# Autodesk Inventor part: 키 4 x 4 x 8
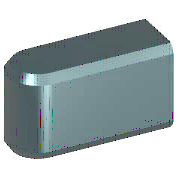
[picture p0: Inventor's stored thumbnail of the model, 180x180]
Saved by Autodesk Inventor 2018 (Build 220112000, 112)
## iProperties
Created: 2012-02
Part Number: 키 4 x 4 x 8
Material: 강철, 연강
Description: 키 및 해당 키홈
Document SubType Name: Modeling
Standard: KS B 1311
Designer: mduedu
Standards Organization: KS
Language: ko-KR
Size Designation: 4 x 4 x 8
Categories: <MemberInstance><Categories><Category DisplayName="샤프트 부품" InternalName="7f7aeb1f-a693-4053-b835-cee3144e0d98" Mnemonic="SHFT"><Category DisplayName="키" Interna
Density: 7.85 g/cm^3
Appearance: 노란색
Mass: 0.94205 g
Surface Area: 1.44138 cm^2
Volume: 0.120006 cm^3
IsCustomPart: 1
Author: mduedu
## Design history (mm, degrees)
sketch "스케치1"
  geometry: L1 (2, 2)-(8, 2); L2 (8, 2)-(8, -2); L3 (8, -2)-(2, -2); L4 (0, 7)-(0, -7) reference; L5 (-5, 0)-(30, 0) reference; A1 r 2 centre (2, 0) between (2, 2) and (2, -2)
  constraints: 6 end point, 3 tangent, 2 point on circle, 1 centre point, 1 horizontal, 1 parallel, 1 perpendicular, 1 point on line
  dimensions: "d0" = 2 radius of A1 (= 0.5 x PB); "d7" = 8 distance between parallel lines of L2 L4 (= NLG)
workplane "Work Plane1"
workplane "Work Plane2"
extrude "본체1" new body sketch "스케치1" taper "d3" = 0 deg; stored distance "d4" = 10
workaxis "Work Axis1"
workplane "Work Plane4"
body "Solid1"
chamfer "모따기1" distance "d8" = 0.25 (= PHH); stored, may be unused: second distance "d9" = 0.25 (= PHH), angle "d13" = 45 deg
other parameters: "d1" = -2.5 (= -PNT), "d2" = 1.5 (= PH - PNT), "NLG" = 8 [user parameter; used in 2 equation terms], "PB" = 4 [user parameter; used in 1 equation term], "PNT" = 2.5 [user parameter; used in 2 equation terms], "PH" = 4 [user parameter; used in 1 equation term], "PHH" = 0.25 [user parameter; used in 2 equation terms], "d10" = 0, "d16" = 0, "d17" = 0, "d18" = 0, "RR" = 0.08 [user parameter], "WDMAX" = 12 [user parameter], "PLB1" = 8 (= NLG) [user parameter], "PUEB" = 1.8 [user parameter]
